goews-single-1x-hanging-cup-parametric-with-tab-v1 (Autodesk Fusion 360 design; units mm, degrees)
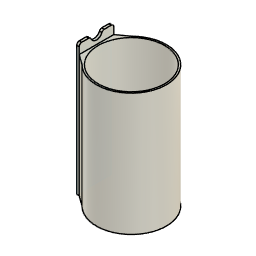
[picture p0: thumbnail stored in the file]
parameter "CupInner_Diam" = 80
parameter "CupWall" = 2
parameter "Height" = 150
parameter "bottomThickness" = 2
base_feature "Base Feature1" bodies "Cup", "Single Plate Blank"
delete_face "DeleteFace1"
base_feature "Base Feature1" bodies "Single Plate Blank"
sketch "Sketch1" plane through (99.15, 0, 0) normal (1, 0, 0) x axis (0, 1, 0)
  line L1 (20.8, -177.7602) -> (20.8, -206.2982)
  line L2 (6.9847, -177.7602) -> (20.8, -177.7602)
  line L3 (-20.8, -177.7602) -> (-6.9847, -177.7602)
  line L4 (-20.8, -206.2982) -> (-20.8, -177.7602)
  line L5 (20.8, -206.2982) -> (-20.8, -206.2982)
  line L6 (6.9847, -177.7602) -> (-6.9847, -177.7602)
  line L7 (0, -184.2983) -> (0, -177.7602)
  arc A1 centre (0, -177.2983) radius 7 clockwise from (6.9847, -177.7602) to (-6.9847, -177.7602)
  point P5 (-6.9847, -177.7602)
  point P9 (-6.9847, -177.7602)
  point P4 (6.9847, -177.7602)
  point P10 (6.9847, -177.7602)
  point P11 (0, -177.7602)
  point P12 (0, -184.2983)
  coincident P5 P9
  coincident P4 P10
  midpoint L6 P11
  midpoint A1 P12
  dimension "d53" distance P11 P12 = 6.5381
extrude "Extrude5" add sketch "Sketch1" profile of A1 L6 L7 against normal blind 3
move_face "MoveFace2"
sketch "Sketch2" plane through (0, 0, -184.2982) normal (0, 0, 1) x axis (-1, 0, 0)
  line L1 (-99.15, -20.8) -> (-99.15, 20.8)
  line L2 (-96.15, -20.8) -> (-99.15, -20.8)
  line L3 (-96.15, 20.8) -> (-96.15, -20.8)
  line L4 (-99.15, 20.8) -> (-96.15, 20.8)
  line L5 (-99.15, 0) -> (-99.15, 20.8)
  line L6 (-196.15, 0) -> (-96.15, 0)
  line L7 (-99.15, 0) -> (-99.15, -20.8)
  line L8 (-99.15, 20.8) -> (-99.15, -20.8)
  line L9 (-99.15, 20.8) -> (-99.15, -20.8)
  line L10 (-111.4515, 29.6985) -> (-141.15, 0)
  line L11 (-99.15, 0) -> (-141.15, 0)
  line L12 (-111.4515, -29.6985) -> (-141.15, 0)
  line L13 (-111.4515, -29.6985) -> (-99.15, -20.8)
  line L14 (-111.4515, 29.6985) -> (-99.15, 20.8)
  circle C1 centre (-141.15, 0) radius 42
  circle C2 centre (-141.15, 0) radius 40
  point P2 (-99.15, 20.8)
  point P8 (-99.15, 20.8)
  point P9 (-99.15, 0)
  point P10 (-96.15, 0)
  point P6 (-141.15, 0)
  point P12 (-99.15, 0)
  point P13 (-99.15, -20.8)
  point P15 (-99.15, -20.8)
  point P17 (-99.15, -20.8)
  point P19 (-99.15, 20.8)
  point P16 (-99.15, 0)
  point P20 (-141.15, 0)
  point P21 (-111.4515, 29.6985)
  point P23 (-141.15, 0)
  point P24 (-111.4515, -29.6985)
  point P25 (-99.15, 20.8)
  point P11 (-196.15, 0)
  coincident P2 P8
  coincident C1 P9
  tangent C1 L5
  midpoint L3 P10
  perpendicular L3 L6
  coincident P6 L6
  coincident C1 P12
  coincident P13 P15
  coincident P13 P17
  tangent C1 L7
  coincident P2 P19
  coincident C1 P16
  horizontal L11
  coincident P6 P20
  coincident C1 P21
  coincident P6 P23
  coincident C1 P24
  coincident P2 P25
  dimension "d40" diameter C1 = 84 (= "CupInner_Diam + ( CupWall * 2 )")
  dimension "d47" distance P10 P11 = 100
  dimension "d56" angle L10 L11 = 45 (= "Angular Dimension-2")
  dimension "d57" angle L10 L12 = 90 (= "Angular Dimension-3")
extrude "Extrude2" add sketch "Sketch2" profile of L1 C1 C2 L5 L7 L8 L9 L13 L14
sketch "Sketch4" plane through (0, 0, -336.2982) normal (0, 0, -1) x axis (1, 0, 0)
  line L1 (96.15, 20.8) -> (99.15, 20.8)
  line L2 (96.15, -20.8) -> (96.15, 20.8)
  line L3 (99.15, -20.8) -> (96.15, -20.8)
  line L4 (111.4515, -29.6985) -> (99.15, -20.8)
  line L5 (99.15, 20.8) -> (111.4515, 29.6985)
  circle C1 centre (141.15, 0) radius 40
  arc A1 centre (141.15, 0) radius 42 clockwise from (111.4515, 29.6985) to (111.4515, -29.6985)
extrude "Extrude7" add sketch "Sketch4" profile of C1
sketch "Sketch5" plane through (96.15, 0, 0) normal (-1, 0, 0) x axis (0, -1, 0)
  line L1 (-20.8, -336.2982) -> (-20.8, -184.2982)
  line L2 (20.8, -336.2982) -> (-20.8, -336.2982)
  line L3 (20.8, -184.2982) -> (20.8, -336.2982)
  line L4 (-20.8, -184.2982) -> (20.8, -184.2982)
  line L5 (-15.3, -202.15) -> (15.3, -202.15)
  line L6 (-15.3, -189) -> (-15.3, -202.15)
  line L7 (-9.0624, -189) -> (-15.3, -189)
  line L8 (15.3, -189) -> (9.0624, -189)
  line L9 (15.3, -202.15) -> (15.3, -189)
  arc A1 centre (0, -186.15) radius 9.5 clockwise from (9.0624, -189) to (-9.0624, -189)
extrude "Extrude8" cut of existing geometry blind -4.7018
combine "Combine1"
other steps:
create_component "CreateComponent1"
remove_body "RemoveBody1"
named bodies: "Cup", "Single Plate Blank"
